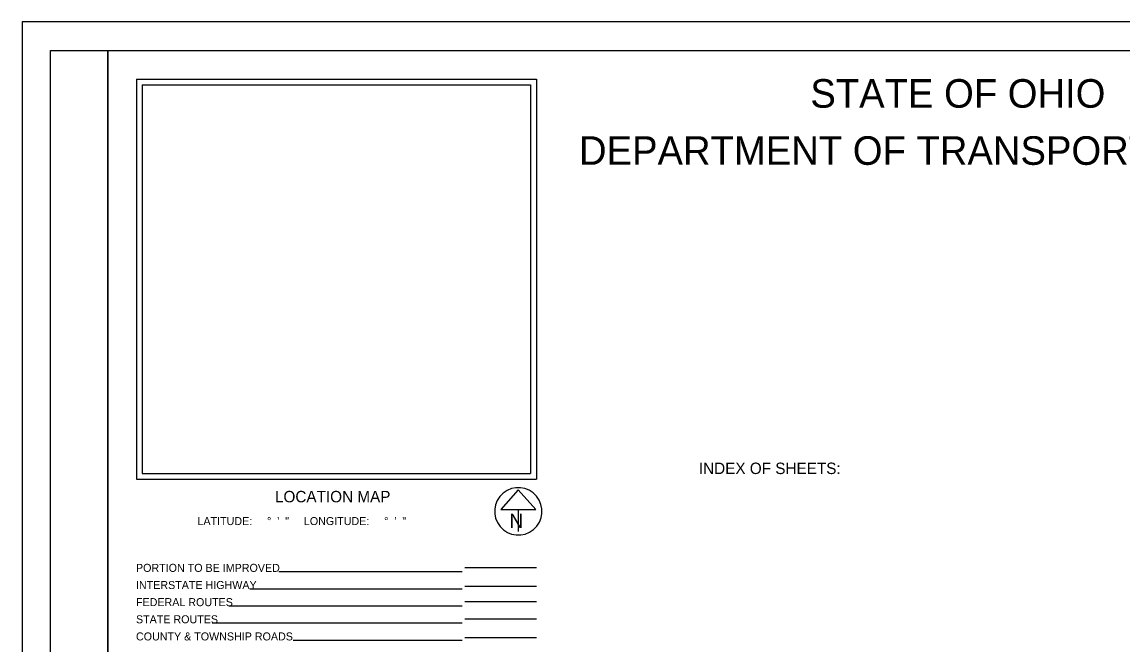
# Model space of a CAD drawing. Extents: x 0 to 44, y -23.8 to 22.
# Drawn here: x 10.02 to 29.29, y -12.69 to -1.79 of the extents above; entities that cross this region are included whole.
import ezdxf

# ---------------------------------------------------------------- set-up
doc = ezdxf.new("R2010")
doc.units = 0
for name, color, linetype in [('SH_Border', 7, 'Continuous'), ('SH_Cut_Line', 7, 'Continuous'), ('SH_Data', 7, 'Continuous'), ('SH_Text', 7, 'Continuous')]:
    doc.layers.add(name, color=color, linetype=linetype)

msp = doc.modelspace()

# ---------------------------------------------------------------- linework, layer by layer
at = {"layer": 'SH_Border'}
for points in [[(10.525, -2.285), (11.525, -2.285), (11.525, -23.285), (10.525, -23.285)], [(11.525, -2.285), (43.525, -2.285), (43.525, -23.285), (11.525, -23.285)]]:
    msp.add_lwpolyline(points, close=True, dxfattribs=at)
at = {"layer": 'SH_Cut_Line'}
msp.add_lwpolyline([(10.025, -23.785), (44.025, -23.785), (44.025, -1.785), (10.025, -1.785)], close=True, dxfattribs=at)
at = {"layer": 'SH_Data'}
for p, q in [((12.025, -2.785), (19.025, -2.785)), ((12.025, -2.785), (12.025, -9.785)), ((12.125, -2.885), (12.125, -9.685)), ((12.125, -2.885), (18.925, -2.885)), ((18.925, -2.885), (18.925, -9.685)), ((19.025, -2.785), (19.025, -9.785)), ((12.025, -9.785), (19.025, -9.785)), ((12.125, -9.685), (18.925, -9.685)), ((12.125, -9.685), (12.125, -9.685)), ((18.709, -9.976), (18.401, -10.318)), ((19.017, -10.318), (18.709, -9.976)), ((18.401, -10.318), (19.017, -10.318)), ((18.709, -10.318), (18.709, -10.704)), ((18.709, -10.35), (18.709, -10.35)), ((18.709, -10.35), (18.709, -10.35)), ((17.775, -11.33), (19.025, -11.33)), ((17.725, -11.409), (14.518, -11.409)), ((17.725, -11.709), (14.014, -11.709)), ((19.025, -11.665), (17.775, -11.665)), ((19.025, -11.936), (17.775, -11.936)), ((17.725, -12.009), (13.644, -12.009)), ((17.725, -12.309), (13.353, -12.309)), ((19.025, -12.236), (17.775, -12.236)), ((17.725, -12.609), (14.77, -12.609)), ((19.025, -12.563), (17.775, -12.563))]:
    msp.add_line(p, q, dxfattribs=at)
msp.add_arc((18.709, -10.35), 0.415, 129.7798, 129.7633, dxfattribs=at)

# ---------------------------------------------------------------- texts
msp.add_text('N', height=0.25, dxfattribs=at).set_placement((18.554, -10.642))
at = {"layer": 'SH_Text'}
for s, height, p in [('STATE OF OHIO', 0.5, (23.82, -3.285)), ('DEPARTMENT OF TRANSPORTATION', 0.5, (19.771, -4.285)), ('INDEX OF SHEETS:', 0.2, (21.869, -9.697)), ('LOCATION MAP', 0.2, (14.451, -10.192)), ('LATITUDE:     °  \'  "     LONGITUDE:     °  \'  "', 0.14, (13.095, -10.59)), ('PORTION TO BE IMPROVED', 0.14, (12.019, -11.409)), ('INTERSTATE HIGHWAY', 0.14, (12.019, -11.709)), ('FEDERAL ROUTES', 0.14, (12.019, -12.009)), ('STATE ROUTES', 0.14, (12.019, -12.309)), ('COUNTY & TOWNSHIP ROADS', 0.14, (12.019, -12.609))]:
    msp.add_text(s, height=height, dxfattribs=at).set_placement(p)

doc.saveas('drawing.dxf')
